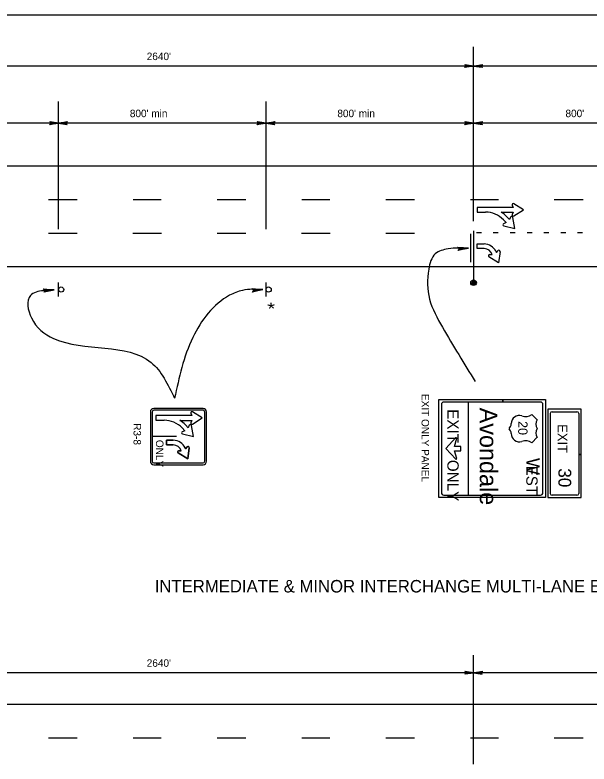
# Model space of a CAD drawing. Extents: x 644898 to 648326, y 298294 to 300670.
# Drawn here: x 645103.8 to 645333.7, y 298573.8 to 298873.5 of the extents above; entities that cross this region are included whole.
import ezdxf

# ---------------------------------------------------------------- set-up
doc = ezdxf.new("R2010")
doc.units = 0
doc.layers.add('1', color=7, linetype='Continuous')
doc.layers.add('2', color=7, linetype='Continuous')

msp = doc.modelspace()

# ---------------------------------------------------------------- linework, layer by layer
at = {"layer": '1'}
msp.add_line((644938.32, 298873.49), (645724.32, 298873.49), dxfattribs=at)
at = {"layer": '2'}
for p, q in [((645287.45, 298791.02), (645287.45, 298860.69)), ((645284.08, 298853.56), (645283.95, 298853.69)), ((645283.95, 298853.69), (645287.45, 298853.06)), ((645284.08, 298853.56), (645284.2, 298853.31)), ((645287.45, 298853.06), (645284.08, 298853.56)), ((645284.2, 298853.31), (645287.45, 298853.06)), ((645287.45, 298853.06), (645290.95, 298853.69)), ((645290.83, 298853.44), (645287.45, 298853.06)), ((645290.7, 298853.19), (645290.83, 298853.44)), ((645290.95, 298853.69), (645290.83, 298853.44)), ((645287.45, 298853.06), (645038.18, 298853.06)), ((645287.45, 298853.06), (645283.95, 298852.44)), ((645283.95, 298852.44), (645284.08, 298852.69)), ((645284.08, 298852.69), (645287.45, 298853.06)), ((645284.2, 298852.94), (645284.08, 298852.69)), ((645287.45, 298853.06), (645284.2, 298852.94)), ((645287.45, 298853.06), (645290.7, 298853.19)), ((645290.7, 298852.81), (645287.45, 298853.06)), ((645287.45, 298853.06), (645290.83, 298852.56)), ((645290.95, 298852.44), (645287.45, 298853.06)), ((645536.72, 298853.06), (645287.45, 298853.06)), ((645290.83, 298852.56), (645290.7, 298852.81)), ((645290.83, 298852.56), (645290.95, 298852.44)), ((645121.27, 298787.81), (645121.27, 298838.91)), ((645204.36, 298787.81), (645204.36, 298838.91)), ((645121.27, 298830.22), (645038.18, 298830.22)), ((645117.9, 298830.72), (645117.77, 298830.85)), ((645117.77, 298830.85), (645121.27, 298830.22)), ((645121.27, 298830.22), (645117.77, 298829.6)), ((645117.77, 298829.6), (645117.9, 298829.85)), ((645117.9, 298830.72), (645118.02, 298830.47)), ((645121.27, 298830.22), (645117.9, 298830.72)), ((645117.9, 298829.85), (645121.27, 298830.22)), ((645118.02, 298830.1), (645117.9, 298829.85)), ((645118.02, 298830.47), (645121.27, 298830.22)), ((645121.27, 298830.22), (645118.02, 298830.1)), ((645121.27, 298830.22), (645124.77, 298830.85)), ((645124.65, 298830.6), (645121.27, 298830.22)), ((645121.27, 298830.22), (645124.52, 298830.35)), ((645204.36, 298830.22), (645121.27, 298830.22)), ((645124.52, 298829.97), (645121.27, 298830.22)), ((645121.27, 298830.22), (645124.65, 298829.72)), ((645124.77, 298829.6), (645121.27, 298830.22)), ((645124.52, 298830.35), (645124.65, 298830.6)), ((645124.65, 298829.72), (645124.52, 298829.97)), ((645124.77, 298830.85), (645124.65, 298830.6)), ((645124.65, 298829.72), (645124.77, 298829.6)), ((645200.99, 298830.72), (645200.86, 298830.85)), ((645200.86, 298830.85), (645204.36, 298830.22)), ((645204.36, 298830.22), (645200.86, 298829.6)), ((645200.86, 298829.6), (645200.99, 298829.85)), ((645200.99, 298830.72), (645201.11, 298830.47)), ((645204.36, 298830.22), (645200.99, 298830.72)), ((645200.99, 298829.85), (645204.36, 298830.22)), ((645201.11, 298830.1), (645200.99, 298829.85)), ((645201.11, 298830.47), (645204.36, 298830.22)), ((645204.36, 298830.22), (645201.11, 298830.1)), ((645204.36, 298830.22), (645207.86, 298830.85)), ((645207.74, 298830.6), (645204.36, 298830.22)), ((645204.36, 298830.22), (645207.61, 298830.35)), ((645287.45, 298830.22), (645204.36, 298830.22)), ((645207.61, 298829.97), (645204.36, 298830.22)), ((645204.36, 298830.22), (645207.74, 298829.72)), ((645207.86, 298829.6), (645204.36, 298830.22)), ((645207.61, 298830.35), (645207.74, 298830.6)), ((645207.74, 298829.72), (645207.61, 298829.97)), ((645207.86, 298830.85), (645207.74, 298830.6)), ((645207.74, 298829.72), (645207.86, 298829.6)), ((645284.08, 298830.72), (645283.95, 298830.85)), ((645283.95, 298830.85), (645287.45, 298830.22)), ((645287.45, 298830.22), (645283.95, 298829.6)), ((645283.95, 298829.6), (645284.08, 298829.85)), ((645284.08, 298830.72), (645284.2, 298830.47)), ((645287.45, 298830.22), (645284.08, 298830.72)), ((645284.08, 298829.85), (645287.45, 298830.22)), ((645284.2, 298830.1), (645284.08, 298829.85)), ((645284.2, 298830.47), (645287.45, 298830.22)), ((645287.45, 298830.22), (645284.2, 298830.1)), ((645287.45, 298830.22), (645290.95, 298830.85)), ((645290.83, 298830.6), (645287.45, 298830.22)), ((645287.45, 298830.22), (645290.7, 298830.35)), ((645290.7, 298829.97), (645287.45, 298830.22)), ((645287.45, 298830.22), (645290.83, 298829.72)), ((645290.95, 298829.6), (645287.45, 298830.22)), ((645370.54, 298830.22), (645287.45, 298830.22)), ((645290.7, 298830.35), (645290.83, 298830.6)), ((645290.83, 298829.72), (645290.7, 298829.97)), ((645290.95, 298830.85), (645290.83, 298830.6)), ((645290.83, 298829.72), (645290.95, 298829.6)), ((645010.69, 298813.15), (645651.96, 298813.15)), ((645117.28, 298799.69), (645128.78, 298799.69)), ((645151.16, 298799.69), (645162.41, 298799.69)), ((645184.78, 298799.69), (645196.28, 298799.69)), ((645218.66, 298799.69), (645229.91, 298799.69)), ((645252.28, 298799.69), (645263.78, 298799.69)), ((645286.16, 298799.69), (645297.41, 298799.69)), ((645319.78, 298799.69), (645331.28, 298799.69)), ((645303.31, 298796.46), (645288.93, 298796.46)), ((645288.93, 298796.46), (645288.93, 298794.63)), ((645302.93, 298797.44), (645303.31, 298796.46)), ((645307.38, 298795.53), (645303.59, 298797.99)), ((645288.93, 298794.63), (645292.23, 298794.63)), ((645298.52, 298794.59), (645303.31, 298794.59)), ((645303.31, 298794.59), (645302.93, 298793.61)), ((645303.59, 298793.07), (645307.38, 298795.53)), ((645299.42, 298791.53), (645300.49, 298790.4)), ((645300.49, 298790.4), (645299.47, 298789.99)), ((645301.8, 298791.63), (645300.72, 298792.77)), ((645302.26, 298792.63), (645301.8, 298791.63)), ((645303.93, 298788.08), (645303.11, 298792.52)), ((645299.54, 298789.14), (645303.93, 298788.08)), ((645117.28, 298786.19), (645128.78, 298786.19)), ((645151.03, 298786.19), (645162.53, 298786.19)), ((645184.78, 298786.19), (645196.28, 298786.19)), ((645218.53, 298786.19), (645230.03, 298786.19)), ((645252.28, 298786.19), (645263.78, 298786.19)), ((645286.33, 298774.64), (645286.33, 298785.86)), ((645287.45, 298787.18), (645287.45, 298766.3)), ((645290.6, 298786.27), (645288.6, 298786.27)), ((645297.35, 298786.27), (645295.35, 298786.27)), ((645304.1, 298786.27), (645302.1, 298786.27)), ((645310.85, 298786.27), (645308.85, 298786.27)), ((645317.6, 298786.27), (645315.6, 298786.27)), ((645324.35, 298786.27), (645322.35, 298786.27)), ((645331.1, 298786.27), (645329.1, 298786.27)), ((645010.69, 298772.9), (645442.59, 298772.9)), ((645121.27, 298760.83), (645121.27, 298766.45)), ((645204.36, 298760.83), (645204.36, 298766.45)), ((645288.2, 298766.55), (645286.58, 298766.17)), ((645287.33, 298765.55), (645286.58, 298766.42)), ((645286.58, 298766.42), (645287.95, 298765.55)), ((645287.95, 298767.05), (645286.7, 298766.67)), ((645286.7, 298766.67), (645288.2, 298766.55)), ((645286.83, 298767.05), (645287.95, 298767.05)), ((645287.95, 298765.55), (645287.33, 298767.3)), ((645287.33, 298767.3), (645288.45, 298766.17)), ((645288.45, 298766.17), (645287.95, 298767.17)), ((645286.58, 298766.17), (645288.45, 298766.17)), ((645288.45, 298766.17), (645286.7, 298765.8)), ((645286.7, 298765.8), (645288.2, 298765.8)), ((645288.2, 298765.8), (645287.33, 298765.55)), ((645287.45, 298766.3), (645287.45, 298766.3)), ((645273.57, 298680.37), (645273.57, 298719.62)), ((645273.57, 298719.62), (645299.13, 298719.62)), ((645299.13, 298718.62), (645275.57, 298718.62)), ((645299.13, 298718.62), (645299.13, 298719.62)), ((645299.13, 298719.62), (645316.2, 298719.62)), ((645299.13, 298719.62), (645299.13, 298718.62)), ((645314.2, 298718.62), (645299.13, 298718.62)), ((645316.2, 298719.62), (645316.2, 298680.37)), ((645274.57, 298717.62), (645274.57, 298682.37)), ((645315.2, 298682.37), (645315.2, 298717.62)), ((645330.57, 298715.75), (645317.2, 298715.75)), ((645317.2, 298715.75), (645317.2, 298680.37)), ((645330.57, 298697.68), (645330.57, 298715.75)), ((645174.67, 298713.18), (645160.28, 298713.18)), ((645160.28, 298713.18), (645160.28, 298711.34)), ((645174.28, 298714.16), (645174.67, 298713.18)), ((645178.73, 298712.24), (645174.94, 298714.7)), ((645310.82, 298713.62), (645312.95, 298711.5)), ((645318.2, 298682), (645318.2, 298714)), ((645318.95, 298714.75), (645328.82, 298714.75)), ((645329.57, 298714), (645329.57, 298697.68)), ((645160.28, 298711.34), (645163.58, 298711.34)), ((645169.87, 298711.3), (645174.67, 298711.3)), ((645173.15, 298708.35), (645172.08, 298709.48)), ((645174.67, 298711.3), (645174.28, 298710.32)), ((645174.94, 298709.78), (645178.73, 298712.24)), ((645302.45, 298710), (645302.45, 298710)), ((645170.77, 298708.24), (645171.84, 298707.11)), ((645171.84, 298707.11), (645170.83, 298706.7)), ((645173.61, 298709.34), (645173.15, 298708.35)), ((645175.28, 298704.79), (645174.46, 298709.23)), ((645307.2, 298708), (645307.2, 298708)), ((645307.2, 298708), (645307.2, 298708)), ((645307.2, 298708), (645307.2, 298708)), ((645307.2, 298708), (645307.2, 298708)), ((645307.2, 298708), (645307.2, 298708)), ((645170.89, 298705.85), (645175.28, 298704.79)), ((645280.32, 298704.37), (645276.32, 298700)), ((645279.82, 298700.87), (645280.7, 298704.12)), ((645302.45, 298705.87), (645302.45, 298705.87)), ((645305.2, 298705.75), (645305.2, 298705.75)), ((645312.95, 298704.5), (645310.82, 298702.25)), ((645282.32, 298699.12), (645282.32, 298700.87)), ((645305.82, 298702.75), (645305.82, 298702.75)), ((645276.32, 298700), (645280.32, 298695.75)), ((645280.7, 298696), (645279.82, 298699.12)), ((645293.45, 298700.12), (645293.45, 298700.12)), ((645329.57, 298697.68), (645330.57, 298697.68)), ((645330.57, 298697.68), (645329.57, 298697.68)), ((645329.57, 298697.68), (645329.57, 298682)), ((645330.57, 298680.37), (645330.57, 298697.68)), ((645316.2, 298680.37), (645273.57, 298680.37)), ((645275.57, 298681.37), (645314.2, 298681.37)), ((645317.2, 298680.37), (645330.57, 298680.37)), ((645328.82, 298681.37), (645318.95, 298681.37)), ((645287.45, 298573.78), (645287.45, 298617.3)), ((645284.08, 298610.8), (645283.95, 298610.93)), ((645283.95, 298610.93), (645287.45, 298610.3)), ((645284.08, 298610.8), (645284.2, 298610.55)), ((645287.45, 298610.3), (645284.08, 298610.8)), ((645284.2, 298610.55), (645287.45, 298610.3)), ((645287.45, 298610.3), (645290.95, 298610.93)), ((645290.83, 298610.68), (645287.45, 298610.3)), ((645290.7, 298610.43), (645290.83, 298610.68)), ((645290.95, 298610.93), (645290.83, 298610.68)), ((645287.45, 298610.3), (645038.18, 298610.3)), ((645287.45, 298610.3), (645283.95, 298609.68)), ((645283.95, 298609.68), (645284.08, 298609.93)), ((645284.08, 298609.93), (645287.45, 298610.3)), ((645284.2, 298610.18), (645284.08, 298609.93)), ((645287.45, 298610.3), (645284.2, 298610.18)), ((645287.45, 298610.3), (645290.7, 298610.43)), ((645290.7, 298610.05), (645287.45, 298610.3)), ((645287.45, 298610.3), (645290.83, 298609.8)), ((645290.95, 298609.68), (645287.45, 298610.3)), ((645536.72, 298610.3), (645287.45, 298610.3)), ((645290.83, 298609.8), (645290.7, 298610.05)), ((645290.83, 298609.8), (645290.95, 298609.68)), ((645010.69, 298597.76), (645651.96, 298597.76)), ((645117.28, 298584.3), (645128.78, 298584.3)), ((645151.16, 298584.3), (645162.41, 298584.3)), ((645184.78, 298584.3), (645196.28, 298584.3)), ((645218.66, 298584.3), (645229.91, 298584.3)), ((645252.28, 298584.3), (645263.78, 298584.3)), ((645286.16, 298584.3), (645297.41, 298584.3)), ((645319.78, 298584.3), (645331.28, 298584.3))]:
    msp.add_line(p, q, dxfattribs=at)
for points in [[(645291.65, 298780), (645288.93, 298780), (645288.93, 298781.87), (645291.65, 298781.87)], [(645281.29, 298780.35), (645281.42, 298780.23), (645285.42, 298780.23), (645281.29, 298780.35), (645281.04, 298780.6), (645285.42, 298780.23), (645281.54, 298779.73), (645281.42, 298779.48), (645285.42, 298780.23), (645281.29, 298779.23), (645281.42, 298779.48)], [(645298.04, 298778.84), (645297.41, 298774.37), (645293.58, 298776.77)], [(645296.42, 298778.8), (645296.57, 298778.48), (645297.27, 298779.21)], [(645293.79, 298777.59), (645294.86, 298777.66)], [(645115.33, 298763.65), (645115.46, 298763.52), (645119.46, 298763.52), (645115.33, 298763.65), (645115.08, 298763.9), (645119.46, 298763.52), (645115.58, 298763.02), (645115.46, 298762.77), (645119.46, 298763.52), (645115.33, 298762.52), (645115.46, 298762.77)], [(645198.93, 298763.76), (645199.06, 298763.63), (645203.06, 298763.63), (645198.93, 298763.76), (645198.68, 298764.01), (645203.06, 298763.63), (645199.18, 298763.13), (645199.06, 298762.88), (645203.06, 298763.63), (645198.93, 298762.63), (645199.06, 298762.88)], [(645285.32, 298718.62), (645285.32, 298681.37)], [(645179.12, 298716.04), (645159.44, 298716.04)], [(645158.03, 298714.63), (645158.03, 298694.94)], [(645158.73, 298714.63), (645158.73, 298694.94)], [(645179.12, 298715.33), (645159.44, 298715.33)], [(645174.28, 298714.16), (645174.67, 298713.18), (645160.28, 298713.18), (645160.28, 298711.34)], [(645174.94, 298709.78), (645178.73, 298712.24), (645174.94, 298714.7)], [(645179.83, 298694.94), (645179.83, 298714.63)], [(645180.53, 298694.94), (645180.53, 298714.63)], [(645160.28, 298711.34), (645163.58, 298711.34)], [(645169.87, 298711.3), (645174.67, 298711.3), (645174.28, 298710.32)], [(645173.61, 298709.34), (645173.15, 298708.35), (645172.08, 298709.48)], [(645170.77, 298708.24), (645171.84, 298707.11), (645170.83, 298706.7)], [(645170.89, 298705.85), (645175.28, 298704.79), (645174.46, 298709.23)], [(645168.53, 298704.79), (645158.73, 298704.79)], [(645167.21, 298701.46), (645164.49, 298701.46), (645164.49, 298703.33), (645167.21, 298703.33)], [(645164.49, 298703.33), (645164.49, 298701.46), (645167.21, 298701.46)], [(645167.21, 298703.33), (645164.49, 298703.33)], [(645171.99, 298700.26), (645172.14, 298699.94), (645172.83, 298700.68)], [(645172.83, 298700.68), (645172.14, 298699.94), (645171.99, 298700.26)], [(645282.32, 298700.87), (645279.82, 298700.87)], [(645173.6, 298700.31), (645172.98, 298695.83), (645169.15, 298698.23)], [(645169.15, 298698.23), (645172.98, 298695.83), (645173.6, 298700.31)], [(645169.36, 298699.06), (645170.42, 298699.12)], [(645170.42, 298699.12), (645169.36, 298699.06)], [(645279.82, 298699.12), (645282.32, 298699.12)], [(645159.44, 298694.24), (645179.12, 298694.24)], [(645159.44, 298693.54), (645179.12, 298693.54)]]:
    msp.add_lwpolyline(points, dxfattribs=at)
for centre, radius in [((645287.44, 298766.36), 1.12), ((645122.31, 298763.64), 1.03), ((645205.4, 298763.64), 1.03)]:
    msp.add_circle(centre, radius, dxfattribs=at)
for centre, radius, start, end in [((645303.34, 298797.61), 0.448, 57.025, 201.6038), ((645292.23, 298784.73), 9.9, 43.4316, 90), ((645292.23, 298784.73), 11.7, 43.4316, 57.4528), ((645303.34, 298793.44), 0.448, 158.3962, 302.975), ((645302.67, 298792.44), 0.448, 10.4566, 155.0355), ((645299.64, 298789.57), 0.448, 111.8278, 256.4066), ((645291.65, 298776.62), 5.25, 24.5121, 90), ((645291.65, 298776.62), 3.38, 17.8867, 90), ((645297.59, 298778.91), 0.448, 352.025, 136.6038), ((645293.82, 298777.15), 0.448, 93.3962, 237.975), ((645275.57, 298717.62), 1, 90, 180), ((645314.2, 298717.62), 1, 360, 90), ((645159.44, 298714.63), 1.41, 90, 180), ((645179.12, 298714.63), 1.41, 360, 90), ((645159.44, 298714.63), 0.703, 90, 180), ((645174.7, 298714.32), 0.448, 57.025, 201.6038), ((645174.7, 298714.32), 0.448, 57.025, 201.6038), ((645179.12, 298714.63), 0.703, 360, 90), ((645305.76, 298709.98), 3.26, 71.452, 179.9953), ((645308.21, 298717.4), 4.55, 251.8289, 304.5747), ((645163.58, 298701.44), 9.9, 43.4316, 90), ((645163.58, 298701.44), 9.9, 43.4316, 90), ((645163.58, 298701.44), 11.7, 43.4316, 57.4528), ((645163.58, 298701.44), 11.7, 43.4316, 57.4528), ((645174.02, 298709.15), 0.448, 10.4566, 155.0355), ((645174.02, 298709.15), 0.448, 10.4566, 155.0355), ((645174.7, 298710.16), 0.448, 158.3962, 302.975), ((645174.7, 298710.16), 0.448, 158.3962, 302.975), ((645299.74, 298709.98), 2.76, 313.7275, 0), ((645315.31, 298709.73), 2.93, 143.136, 216.864), ((645170.99, 298706.29), 0.448, 111.8278, 256.4066), ((645170.99, 298706.29), 0.448, 111.8278, 256.4066), ((645299.74, 298705.97), 2.76, 0, 46.2725), ((645315.31, 298706.22), 2.93, 143.136, 216.864), ((645280.47, 298704.14), 0.217, 345.9638, 136.9667), ((645305.76, 298705.97), 3.26, 180.0047, 288.548), ((645167.21, 298698.08), 5.25, 24.5121, 90), ((645167.21, 298698.08), 5.25, 24.5121, 90), ((645167.21, 298698.08), 3.38, 17.8867, 90), ((645167.21, 298698.08), 3.38, 17.8867, 90), ((645173.16, 298700.37), 0.448, 352.025, 136.6038), ((645173.16, 298700.37), 0.448, 352.025, 136.6038), ((645308.21, 298698.55), 4.55, 55.4253, 108.1711), ((645169.38, 298698.61), 0.448, 93.3962, 237.975), ((645169.38, 298698.61), 0.448, 93.3962, 237.975), ((645159.44, 298694.94), 1.41, 180, 270), ((645159.44, 298694.94), 0.703, 180, 270), ((645179.12, 298694.94), 1.41, 270, 360), ((645179.12, 298694.94), 0.703, 270, 360), ((645280.47, 298695.93), 0.217, 223.0251, 14.0537), ((645275.57, 298682.37), 1, 180, 270), ((645314.2, 298682.37), 1, 270, 0)]:
    msp.add_arc(centre, radius, start, end, dxfattribs=at)
for centre, major_axis, start_param, end_param in [((645318.96, 298714.04), (-0.792, 0), 4.712389, 6.283185), ((645328.81, 298714.04), (-0.792, 0), 3.141593, 4.712389), ((645318.96, 298682.01), (0.792, 0), 3.141593, 4.712389), ((645328.81, 298682.01), (0.792, 0), 4.712389, 6.283185)]:
    msp.add_ellipse(centre, major_axis=major_axis, ratio=0.827467, start_param=start_param, end_param=end_param, dxfattribs=at)
for points in [[(645285.42, 298780.23), (645277.24, 298779.89), (645272.13, 298777.94), (645269.49, 298771.78), (645269.82, 298759.79), (645274.99, 298748.57), (645288.1, 298726.82)], [(645117.37, 298763.36), (645115.13, 298763.18), (645110.02, 298761.23), (645110.4, 298752.27), (645119.24, 298744.05), (645158.33, 298734.49), (645167.75, 298720.13)], [(645203.06, 298763.63), (645194.88, 298763.29), (645189.77, 298761.34), (645175.01, 298744.44), (645167.75, 298720.13)]]:
    msp.add_spline(points, degree=3, dxfattribs=at)

# ---------------------------------------------------------------- texts
for s, height, rotation, p in [("2640'", 3, 360, (645156.58, 298855.44)), ("800' min ", 3, 360, (645149.82, 298832.6)), ("800' min ", 3, 360, (645232.91, 298832.6)), ("800'", 3, 360, (645324.26, 298832.6)), ('*', 5.42, 75.7789, (645209.92, 298754.78)), ('EXIT ONLY PANEL', 3, 270, (645266.63, 298721.85)), ('Avondale', 7, 270, (645289.95, 298716.37)), ('EXIT    ONLY', 4.5457, 270, (645276.95, 298715.75)), ('R3-8', 3, 270, (645151.29, 298710.14)), ('20', 3.75, 270, (645305.32, 298711)), ('EXIT', 3.875, 270, (645321.11, 298709.75)), ('ONLY', 3, 270, (645160.28, 298703.48)), ('W', 5.38, 270, (645308.57, 298696.25)), ('EST', 4.5, 270, (645308.57, 298693.12)), ('30', 5.125, 270, (645321.42, 298692.12)), ("2640'", 3, 360, (645156.58, 298612.68))]:
    msp.add_text(s, height=height, rotation=rotation, dxfattribs=at).set_placement(p)
msp.add_text('INTERMEDIATE & MINOR INTERCHANGE MULTI-LANE EXITS WITH AN OPTION LANE', height=5, dxfattribs=at).set_placement((645159.79, 298642.42))

doc.saveas('drawing.dxf')
